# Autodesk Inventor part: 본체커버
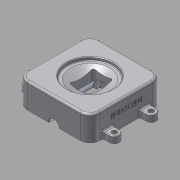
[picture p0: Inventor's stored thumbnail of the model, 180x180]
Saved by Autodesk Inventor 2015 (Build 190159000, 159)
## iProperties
Created: 2018-01
Part Number: 본체커버
Material: 알루미늄 6061
Document SubType Name: Modeling
Designer: mduedu
Density: 1 g/cm^3
Appearance: 알루미늄 - 평지
Author: mduedu
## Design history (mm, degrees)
sketch "스케치1"
  geometry: L1 (55, 55)-(-55, 55); L2 (-55, 55)-(-55, -55); L3 (-55, -55)-(55, -55); L4 (55, -55)-(55, 55); L5 (55, 55)-(-55, -55); L6 (-55, 55)-(55, -55); 1 further point
  constraints: 12 end point, 2 midpoint, 2 parallel, 1 horizontal, 1 perpendicular
  dimensions: "d0" = 110 distance of L3.end L2.end; "d1" = 110 distance of L2.end L1.end
extrude "돌출1" new body sketch "스케치1" distance "d2" = 38; taper "d3" = 0 deg
sketch "스케치2"
  geometry: L1 (-55, 55)-(55, 55) reference; L2 (-55, -55)-(-55, 55) reference; L3 (55, -55)-(-55, -55) reference; L4 (55, 55)-(55, -55) reference; L5 (0, 55)-(7.5, 55); L6 (7.5, 55)-(7.5, 36); L7 (7.5, 36)-(0, 36); L8 (0, 36)-(0, 55); L9 (0, 36)-(16, 36); L10 (16, 36)-(16, 22); L11 (16, 22)-(0, 22); L12 (0, 22)-(0, 36); L13 (0, 22)-(20, 22); L14 (20, 22)-(20, -25); L15 (20, -25)-(0, -25); L16 (0, -25)-(0, 22); L17 (0, -25)-(15, -25); L18 (15, -25)-(15, -30); L19 (15, -30)-(0, -30); L20 (0, -30)-(0, -25); 1 further point
  constraints: 32 end point, 8 parallel, 4 horizontal, 4 perpendicular, 1 midpoint
  dimensions: "d4" = 15 diameter of L6 L8; "d6" = 32 diameter of L10 L12; "d7" = 40 diameter of L14 L16; "d8" = 30 diameter of L18 L20; "d9" = 5 distance of L17.end L18.end; "d10" = 47 distance of L13.end L14.end; "d11" = 14 distance of L9.end L10.end; "d12" = 19 distance of L5.end L6.end
revolve "회전1" sketch "스케치2" stored, may be unused: angle "d13" = 90 deg
fillet "모깎기1" dims "d14" = 1
fillet "모깎기2" dims "d15" = 15
fillet "모깎기3" dims "d16" = 3
sketch "스케치3"
  geometry: L1 (-15, -17)-(15, -17); L2 (15, -17)-(15, 20); L3 (15, 20)-(-15, 20); L4 (-15, 20)-(-15, -17); L5 (-19, -22)-(19, -22) reference; L6 (19, 25)-(-19, 25) reference; 2 further points
  constraints: 8 end point, 2 parallel, 1 horizontal, 1 midpoint, 1 perpendicular, 1 vertical alignment
  dimensions: "d17" = 5 distance between parallel lines of L1 L5; "d18" = 5 distance between parallel lines of L6 L3; "d19" = 37 distance of L3.end L1.start (derived); "d20" = 30 distance between parallel lines of L2 L4
extrude "돌출2" cut sketch "스케치3" stored distance "d21" = 38; taper "d22" = 0 deg
fillet "모깎기4" dims "d23" = 3
sketch "스케치4"
  geometry: L1 (38, 35)-(33, 35); L2 (33, 35)-(33, 30); L3 (33, 30)-(26, 15); L4 (26, 15)-(26, 0); L5 (26, 0)-(38, 0); L6 (38, 0)-(38, 35); L7 (38, 40)-(38, -40) reference; 1 further point
  constraints: 12 end point, 2 parallel, 1 collinear, 1 horizontal, 1 horizontal alignment, 1 perpendicular
  dimensions: "d24" = 5 distance of L1.start L1.end; "d26" = 70 diameter of L1 L5; "d28" = 60 diameter of L2.end L5; "d29" = 30 diameter of L3.end L5; "d30" = 7 horizontal distance of L2.end L3.end
revolve "회전2" sketch "스케치4" stored, may be unused: angle "d31" = 90 deg
chamfer "모따기1" distance "d32" = 1; stored, may be unused: second distance "d33" = 2, angle "d34" = 45 deg
fillet "모깎기5" dims "d35" = 1
chamfer "모따기2" distance "d36" = 1; stored, may be unused: second distance "d37" = 2, angle "d38" = 45 deg
sketch "스케치5"
  geometry: L1 (7.5, 54)-(8.5, 55) reference; L2 (7.5, 54)-(7.5, 37) reference; L3 (8.5, 36)-(7.5, 37) reference; L4 (8.5, 36)-(15, 36) reference; L5 (16, 35)-(16, 22) reference; L6 (16, 22)-(19, 22) reference; L7 (20, 21)-(20, -24) reference; L8 (19, -25)-(15, -25) reference; L9 (15, -25)-(15, -29) reference; L10 (14, -30)-(-14, -30) reference; L11 (-15, -29)-(-15, -25) reference; L12 (-15, -25)-(-19, -25) reference; L13 (-20, -24)-(-20, 21) reference; L14 (-19, 22)-(-16, 22) reference; L15 (-16, 22)-(-16, 35) reference; L16 (-15, 36)-(-8.5, 36) reference; L17 (-7.5, 37)-(-8.5, 36) reference; L18 (-7.5, 37)-(-7.5, 54) reference; L19 (-8.5, 55)-(-7.5, 54) reference; L20 (-40, 55)-(-8.5, 55) reference; L21 (-55, -40)-(-55, 40) reference; L22 (40, -55)-(-40, -55) reference; L23 (55, 40)-(55, -40) reference; L24 (8.5, 55)-(40, 55) reference; L25 (55, 35.5)-(65, 35.5); L26 (65, 20.5)-(55, 20.5); L27 (55, 20.5)-(55, 35.5); L28 (55, 40)-(55, -40) reference; A1 r 1 centre (15, 35) between (16, 35) and (15, 36) reference; A2 r 1 centre (19, 21) between (20, 21) and (19, 22) reference; A3 r 1 centre (19, -24) between (19, -25) and (20, -24) reference; A4 r 1 centre (14, -29) between (14, -30) and (15, -29) reference; A5 r 1 centre (-14, -29) between (-15, -29) and (-14, -30) reference; A6 r 1 centre (-19, -24) between (-20, -24) and (-19, -25) reference; A7 r 1 centre (-19, 21) between (-19, 22) and (-20, 21) reference; A8 r 1 centre (-15, 35) between (-15, 36) and (-16, 35) reference; A9 r 15 centre (-40, 40) between (-40, 55) and (-55, 40) reference; A10 r 15 centre (-40, -40) between (-55, -40) and (-40, -55) reference; A11 r 15 centre (40, -40) between (40, -55) and (55, -40) reference; A12 r 15 centre (40, 40) between (55, 40) and (40, 55) reference; A13 r 7.5 centre (65, 28) between (65, 20.5) and (65, 35.5); 1 further point
  constraints: 6 end point, 2 point on circle, 2 tangent, 1 centre point, 1 collinear, 1 horizontal, 1 parallel, 1 point on line
  dimensions: "d39" = 15 distance between parallel lines of L26 L25; "d41" = 28 vertical distance of A13.centre point (0, 0); "d42" = 10 distance from line of A13.centre L23
extrude "돌출3" join sketch "스케치5" distance "d43" = 10; taper "d44" = 0 deg
fillet "모깎기6" dims "d45" = 1
fillet "모깎기7" dims "d46" = 3
sketch "스케치6"
  geometry: A1 r 7.5 centre (-65, 28) between (-65, 35.5) and (-65, 20.5) reference; A2 r 7.5 centre (-65, -28) between (-65, -20.5) and (-65, -35.5) reference; A3 r 7.5 centre (65, -28) between (65, -35.5) and (65, -20.5) reference; A4 r 7.5 centre (65, 28) between (65, 20.5) and (65, 35.5) reference; 5 further points
  constraints: 4 coincident
sketch "스케치7"
  geometry: 4 further points
  constraints: 4 other
hole "구멍1" sketch "스케치7" at (-65, 28), (65, 28), (-65, -28), (65, -28) diameter "d47" = 4.5; stored, may be unused: countersink angle "d51" = 90 deg, drill point angle "d53" = 0 deg; dims "d48" = 6, "d49" = 8, "d50" = 4.6, "d52" = 8
sketch "스케치8"
  geometry: L1 (-95, 35)-(-95, 0) reference; L2 (0, 38)-(-80, 38) reference; 2 further points
  constraints: 1 other
  dimensions: "d54" = 55 distance from line of point (-40, 23) L1; "d55" = 15 distance from line of point (-40, 23) L2
feature "엠보싱1" sketch "스케치8" dims "d0" = 110, "d1" = 110, "d56" = 0.5, "d57" = 0
node "솔리드1"
mirror "대칭1"
mirror "대칭2"
node "투영된 루프1"
node "투영된 루프2"
